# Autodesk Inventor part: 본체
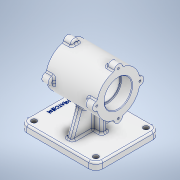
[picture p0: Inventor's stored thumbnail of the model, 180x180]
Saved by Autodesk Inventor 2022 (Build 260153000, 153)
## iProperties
Created: 2023-05
Part Number: 본체
Material: 알루미늄 6061
Document SubType Name: Modeling
Designer: Admin
Density: 2.7 g/cm^3
Appearance: 알루미늄 - 평지
Mass: 1215.34 g
Surface Area: 797.018 cm^2
Volume: 450.125 cm^3
Author: Admin
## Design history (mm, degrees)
sketch "스케치1"
  geometry: L1 (0, -7.4)-(0, 44.4) reference; L2 (-60.9, 0)-(60.9, 0) reference; L3 (-43.5, 0)-(43.5, 0); L4 (43.5, 0)-(43.5, 37); L5 (43.5, 37)-(-43.5, 37); L6 (-43.5, 37)-(-43.5, 0); 2 further points
  constraints: 8 end point, 2 parallel, 1 horizontal, 1 perpendicular, 1 point on line, 1 other
  dimensions: "d4" = 87 distance between parallel lines of L4 L6; "d5" = 74 diameter of L5 L2
revolve "회전1" sketch "스케치1" stored, may be unused: angle "d6" = 90 deg
sketch "스케치2"
  geometry: L1 (-43.5, -37)-(-43.5, 37) reference; L2 (-43.5, 0)-(-24.5, 0); L3 (-24.5, 0)-(-24.5, 23.5); L4 (-24.5, 23.5)-(-43.5, 23.5); L5 (-43.5, 23.5)-(-43.5, 0); L6 (-24.5, 0)-(24.5, 0); L7 (24.5, 0)-(24.5, 21); L8 (24.5, 21)-(-24.5, 21); L9 (-24.5, 21)-(-24.5, 0); L10 (43.5, -37)-(43.5, 37) reference; L11 (24.5, 0)-(43.5, 0); L12 (43.5, 0)-(43.5, 23.5); L13 (43.5, 23.5)-(24.5, 23.5); L14 (24.5, 23.5)-(24.5, 0); L15 (-60.9, 0)-(60.9, 0) reference; 3 further points
  constraints: 24 end point, 6 parallel, 3 horizontal, 3 perpendicular, 2 point on line, 1 midpoint
  dimensions: "d7" = 47 diameter of L4 L15; "d8" = 42 diameter of L8 L15; "d9" = 19 distance between parallel lines of L5 L3; "d10" = 19 distance between parallel lines of L10 L7
revolve "회전2" sketch "스케치2" stored, may be unused: angle "d11" = 90 deg
node "작업 평면1"
sketch "스케치3"
  geometry: L1 (70, -55)-(-60, -55); L2 (-60, -55)-(-60, 55); L3 (-60, 55)-(70, 55); L4 (70, 55)-(70, -55); L5 (89.368, 0)-(-92.632, 0) reference; L6 (0, -67.146)-(0, 86.854) reference; 1 further point
  constraints: 8 end point, 2 parallel, 1 horizontal, 1 perpendicular, 1 other
  dimensions: "d14" = 110 distance between parallel lines of L3 L1; "d58" = 130 distance between parallel lines of L2 L4; "d59" = 70 distance between parallel lines of L6 L4
extrude "돌출1" join sketch "스케치3" distance "d15" = 12; taper "d16" = 0 deg
sketch "스케치4"
  geometry: L1 (-20, 5)-(20, 5); L2 (20, 5)-(20, -5); L3 (20, -5)-(-20, -5); L4 (-20, -5)-(-20, 5); L5 (-96, 0)-(86, 0) reference; L6 (0, 77)-(0, -77) reference; 1 further point
  constraints: 8 end point, 2 parallel, 1 horizontal, 1 perpendicular, 2 other
  dimensions: "d17" = 10 distance between parallel lines of L3 L1; "d18" = 40 distance between parallel lines of L2 L4
extrude "돌출2" join sketch "스케치4" stored distance "d19" = 12; taper "d20" = 0 deg
sketch "스케치5"
  geometry: L1 (0, -105.8)-(0, 60.8) reference; C1 r 7 at (0, 37); 2 further points
  constraints: 1 centre point, 1 point on line, 1 vertical alignment, 1 other
  dimensions: "d21" = 14 diameter of C1
extrude "돌출3" join sketch "스케치5" distance "d22" = 14; taper "d23" = 0 deg
sketch "스케치7"
  geometry: A1 r 7 centre (0, 0) between (6.969, -0.662) and (-6.969, -0.662) reference; A2 r 7 centre (37, -37) between (36.338, -43.969) and (36.338, -30.031) reference; A3 r 7 centre (0, -74) between (-6.969, -73.338) and (6.969, -73.338) reference; A4 r 7 centre (-37, -37) between (-36.338, -30.031) and (-36.338, -43.969) reference; 5 further points
  constraints: 4 coincident
hole "구멍1" sketch "스케치7" at (0, 0), (37, -37), (0, -74), (-37, -37) diameter "d27" = 3.242; stored, may be unused: countersink angle "d31" = 90 deg, drill point angle "d33" = 118 deg; dims "d28" = 8, "d29" = 4, "d30" = 2, "d32" = 10
sketch "스케치8"
  geometry: C1 r 1.621 at (74, 0) reference; C2 r 1.621 at (37, -37) reference; C3 r 1.621 at (0, 0) reference; A1 r 7 centre (37, 37) between (43.969, 36.338) and (30.031, 36.338) reference; A2 r 7 centre (0, 0) between (0.662, 6.969) and (0.662, -6.969) reference; A3 r 7 centre (37, -37) between (30.031, -36.338) and (43.969, -36.338) reference; A4 r 7 centre (74, 0) between (73.338, -6.969) and (73.338, 6.969) reference; 5 further points
  constraints: 4 coincident
hole "구멍2" sketch "스케치8" at (37, 37), (74, 0), (37, -37), (0, 0) diameter "d34" = 3.242; stored, may be unused: countersink angle "d38" = 90 deg, drill point angle "d40" = 118 deg; dims "d35" = 8, "d36" = 4, "d37" = 2, "d39" = 10
sketch "스케치9"
  geometry: L1 (-70, -55)-(-70, 55) reference; L2 (-70, 41)-(-26.964, 25.336); L3 (-82, 55)-(-70, 55) reference; A1 r 37 centre (0, 0) between (-6.969, 36.338) and (-36.338, 6.969) reference; 1 further point
  constraints: 2 end point, 1 point on circle, 1 point on line
  dimensions: "d41" = 110 deg angle of L1 L2; "d42" = 14 distance from line of L2.start L3
feature "리브1" sketch "스케치9" dims "d43" = 1, "d44" = 10, "d45" = 0, "d46" = 0, "d47" = 1, "d48" = 1
fillet "모깎기1" dims "d49" = 12
sketch "스케치10"
  geometry: A1 r 12 centre (-58, 43) between (-58, 55) and (-70, 43) reference; A2 r 12 centre (-58, -43) between (-70, -43) and (-58, -55) reference; A3 r 12 centre (48, 43) between (60, 43) and (48, 55) reference; A4 r 12 centre (48, -43) between (48, -55) and (60, -43) reference; 5 further points
  constraints: 4 coincident
hole "구멍3" sketch "스케치10" at (-58, 43), (48, 43), (48, -43), (-58, -43) diameter "d50" = 9; stored, may be unused: countersink angle "d54" = 90 deg, drill point angle "d56" = 0 deg; dims "d51" = 8, "d52" = 4, "d53" = 2, "d55" = 10
sketch "스케치11"
  geometry: L1 (0, 77)-(0, -77) reference; L2 (-96, 0)-(86, 0) reference; 2 further points
  constraints: 1 other
  dimensions: "d57" = 58 distance from line of L1 point (-58, 1.636)
feature "엠보싱1" dims "d4" = 87, "d5" = 74, "d7" = 47, "d8" = 42, "d9" = 19, "d10" = 19, "d60" = 0.5, "d61" = 0
fillet "모깎기2" dims "d62" = 3
fillet "모깎기3" dims "d63" = 3
fillet "모깎기4" dims "d64" = 1
chamfer "모따기1" distance "d65" = 1; stored, may be unused: second distance "d66" = 2, angle "d67" = 45 deg
node "솔리드1"
pattern_circular "원형 패턴1" dims angle "d25" = 360 deg
mirror "미러1"
mirror "미러2"
feature "A9D066F2-1C7D-4E18-AEED-F7BC21143FA4" dims "d50" = 9, "d51" = 8, "d52" = 4, "d53" = 2, "d54" = 90 deg, "d55" = 10, "d56" = 0
other parameters: "d12" = -82
